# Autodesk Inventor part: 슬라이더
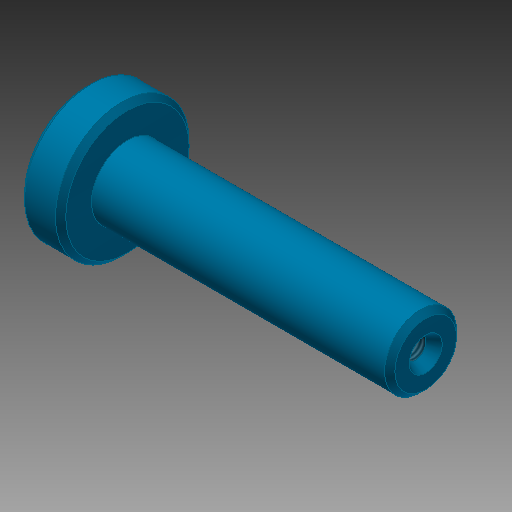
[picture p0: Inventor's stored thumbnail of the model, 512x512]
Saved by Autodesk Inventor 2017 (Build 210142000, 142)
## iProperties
Created: 2020-07
Part Number: 슬라이더
Material: 강철, 연강
Document SubType Name: Modeling
Designer: mduedu
Density: 7.86 g/cm^3
Appearance: 하늘색 중간
Mass: 101.006 g
Surface Area: 43.3118 cm^2
Volume: 12.8506 cm^3
Author: mduedu
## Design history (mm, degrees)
sketch "스케치1"
  geometry: L1 (0, 0)-(8, 0); L2 (8, 0)-(8, 13); L3 (8, 13)-(0, 13); L4 (0, 13)-(0, 0); L5 (8, 0)-(66, 0); L6 (66, 0)-(66, 7); L7 (66, 7)-(8, 7); L8 (8, 7)-(8, 0)
  constraints: 16 end point, 4 parallel, 2 horizontal, 2 perpendicular
  dimensions: "d0" = 66 distance between parallel lines of L6 L4; "d2" = 26 diameter of L3 L1; "d3" = 14 diameter of L7 L5; "d4" = 8 distance of L2.end L3.end
revolve "회전1" sketch "스케치1" stored, may be unused: angle "d5" = 90 deg
chamfer "모따기1" distance "d6" = 1; stored, may be unused: second distance "d7" = 2, angle "d8" = 45 deg
hole "구멍1" diameter "d11" = 4.134; stored, may be unused: countersink angle "d15" = 90 deg, drill point angle "d17" = 118 deg; dims "d9" = 10, "d10" = 10, "d12" = 12, "d13" = 4, "d14" = 2, "d16" = 15
chamfer "모따기2" distance "d18" = 1; stored, may be unused: second distance "d19" = 2, angle "d20" = 45 deg
sketch "스케치2"
  geometry: L1 (51, 2.067)-(66, 2.067) reference; L2 (66, 2.067)-(66, -2.067) reference; L3 (0, 0)-(66, 0); L4 (66, 0)-(64, 0); L5 (64, 0)-(64, 2.067); L6 (66, 3.222)-(66, 0); L7 (66, 3.222)-(64, 2.067)
  constraints: 10 end point, 1 horizontal, 1 midpoint, 1 parallel, 1 perpendicular, 1 point on line
  dimensions: "d21" = 2 horizontal distance of L6.start L5.end; "d23" = 30 deg angle of L7 L3
revolve "회전2" sketch "스케치2" stored, may be unused: angle "d25" = 90 deg
node "솔리드1"
